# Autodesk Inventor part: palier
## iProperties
Created: 2011-01
Part Number: palier
Document SubType Name: Modeling
Designer: eric
Density: 1 g/cm^3
Mass: 18.4809 g
Surface Area: 55.9438 cm^2
Volume: 18.4809 cm^3
Author: eric
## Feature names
1. Base1
